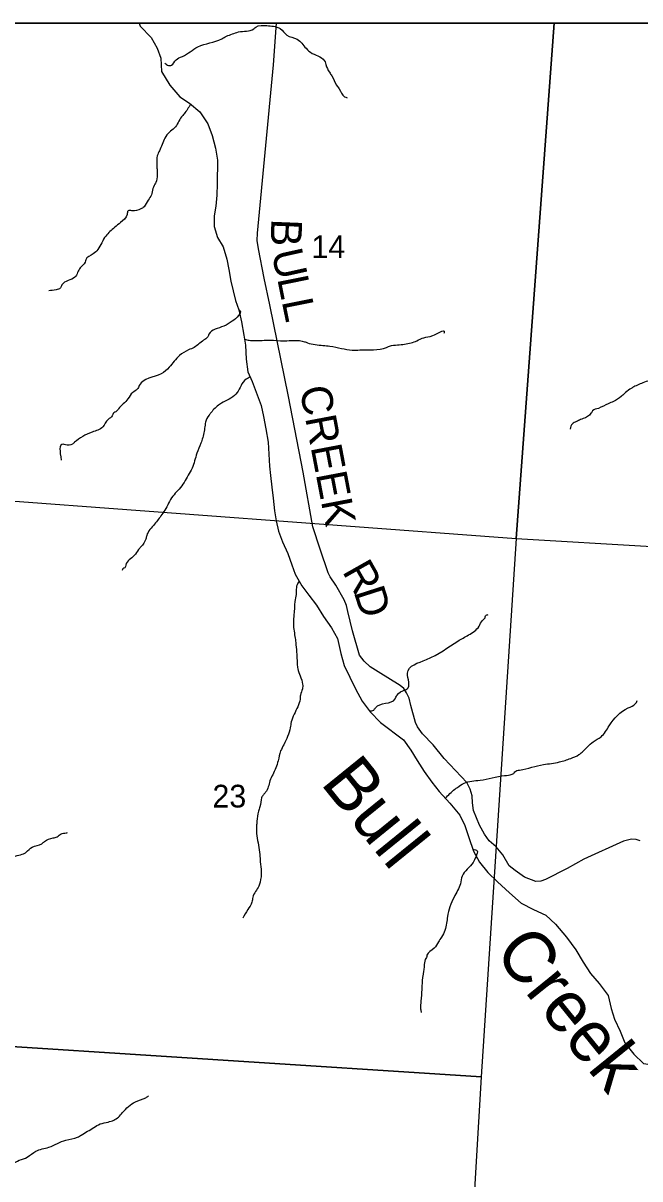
# Model space of a CAD drawing. Extents: x -13.1 to 43.1, y 0 to 22.
# Drawn here: x 5.106 to 6.242, y 18.772 to 20.9 of the extents above; entities that cross this region are included whole.
import ezdxf

# ---------------------------------------------------------------- set-up
doc = ezdxf.new("R2010")
doc.units = 0
for name, color, linetype in [('GM_X_Corporation', 7, 'Continuous'), ('GM_X_Minor_River', 7, 'Continuous'), ('GM_X_Minor_River_Text', 7, 'Continuous'), ('GM_X_Section_Text', 7, 'Continuous'), ('GM_X_Township_Road', 7, 'Continuous'), ('GM_X_Township_Road_Text', 7, 'Continuous'), ('SH_Data', 7, 'Continuous')]:
    doc.layers.add(name, color=color, linetype=linetype)

msp = doc.modelspace()

# ---------------------------------------------------------------- linework, layer by layer
at = {"layer": 'GM_X_Corporation'}
for points in [[(7.0807, 20.9), (2.1, 20.9), (2.1, 14.1), (6.6193, 14.1), (6.6994, 15.2069), (6.7531, 15.956), (6.8236, 16.9075), (6.9509, 19.0179), (7.0108, 19.8446), (7.0164, 19.8954), (7.0617, 20.6133)], [(7.0804, 20.9), (2.1, 20.9), (2.1, 14.1), (6.619, 14.1), (6.6992, 15.2074), (6.7528, 15.9566), (6.8234, 16.908), (6.8365, 17.1257), (6.9507, 19.0184), (6.9616, 19.1692), (7.0106, 19.8452), (7.0162, 19.896), (7.0615, 20.6138)], [(7.0804, 20.9), (2.1, 20.9), (2.1, 17.2152), (2.1437, 17.2135), (2.8442, 17.1637), (3.8328, 17.0966), (4.4304, 17.0575), (6.8234, 16.908), (6.8365, 17.1257), (6.9507, 19.0184), (6.9616, 19.1692), (7.0106, 19.8452), (7.0162, 19.896), (7.0615, 20.6138)], [(6.0839, 20.9), (5.0812, 20.9), (5.0243, 20.0248), (6.0143, 19.9509)], [(7.0765, 20.9), (6.0839, 20.9), (6.0143, 19.9509), (7.0143, 19.8917), (7.0727, 20.8375)], [(5.0243, 20.0248), (6.0143, 19.9509), (5.9495, 18.9594), (4.9602, 19.0234)], [(4.9602, 19.0234), (5.9495, 18.9594), (5.8912, 17.9717), (4.9031, 18.044)]]:
    msp.add_lwpolyline(points, close=True, dxfattribs=at)
at = {"layer": 'GM_X_Minor_River'}
for points in [[(5.3196, 20.9), (5.3212, 20.8944), (5.3415, 20.8738), (5.3527, 20.8539), (5.3593, 20.8357), (5.3606, 20.8106), (5.3763, 20.7855), (5.3943, 20.7641), (5.4124, 20.7525), (5.4312, 20.7365), (5.4462, 20.7143), (5.4543, 20.693), (5.4602, 20.6695), (5.4638, 20.6474), (5.4634, 20.6042), (5.4625, 20.5829), (5.4608, 20.5632), (5.4577, 20.545), (5.4575, 20.5253), (5.4642, 20.5055), (5.4746, 20.488), (5.4812, 20.4652), (5.4849, 20.4462), (5.4885, 20.4249), (5.4929, 20.4067), (5.4973, 20.3892), (5.5032, 20.3717), (5.5083, 20.3496), (5.5127, 20.3253), (5.5155, 20.3071), (5.5168, 20.2813), (5.5197, 20.2577), (5.5279, 20.2402), (5.5442, 20.1961), (5.5485, 20.1756), (5.5529, 20.1528), (5.5573, 20.1284), (5.5599, 20.0844), (5.5613, 20.067), (5.5642, 20.0457), (5.5663, 20.0252), (5.5691, 20.0016), (5.572, 19.9834), (5.5764, 19.9644), (5.5838, 19.9446), (5.5934, 19.9233), (5.6008, 19.9027), (5.6068, 19.8852), (5.6195, 19.8639), (5.6322, 19.8463), (5.6464, 19.828), (5.6591, 19.8074), (5.6741, 19.7861), (5.6853, 19.767), (5.6911, 19.7389), (5.697, 19.7168), (5.7179, 19.6742), (5.7305, 19.6513), (5.7455, 19.6314), (5.7643, 19.6123), (5.8064, 19.5801), (5.8199, 19.561), (5.8319, 19.542), (5.8446, 19.5221), (5.8588, 19.5023), (5.8723, 19.4847), (5.8918, 19.4633), (5.9105, 19.4412), (5.9195, 19.4221), (5.9269, 19.4), (5.9357, 19.3749), (5.9469, 19.3551), (5.9619, 19.336), (5.9799, 19.3184), (6.0017, 19.2985), (6.0235, 19.2794), (6.0462, 19.2678), (6.0688, 19.257), (6.0868, 19.2409), (6.1071, 19.2165), (6.1243, 19.1936), (6.1377, 19.1707), (6.1512, 19.1501), (6.1669, 19.1317), (6.1834, 19.1096), (6.1893, 19.0853), (6.1952, 19.0655), (6.2056, 19.0434)], [(6.2056, 19.0434), (6.2145, 19.0221), (6.231, 19.0015), (6.249, 18.9839), (6.2732, 18.9806), (6.2936, 18.9797), (6.3187, 18.9848), (6.3369, 18.9938), (6.3575, 19.0118), (6.3765, 19.0261), (6.3948, 19.0373), (6.4153, 19.0478), (6.4533, 19.0581), (6.4707, 19.0549), (6.4887, 19.0418), (6.5061, 19.0356), (6.5091, 19.0341)]]:
    msp.add_lwpolyline(points, dxfattribs=at)
for points in [[(5.367, 20.8262), (5.3734, 20.822), (5.3791, 20.8227), (5.3875, 20.8324), (5.3992, 20.8386), (5.4277, 20.8564), (5.4719, 20.8709), (5.4803, 20.8757), (5.4916, 20.8801), (5.5026, 20.8837), (5.5306, 20.8897), (5.5344, 20.8927), (5.5551, 20.8954), (5.5668, 20.8941), (5.5796, 20.8898), (5.5916, 20.8779), (5.6108, 20.8704), (5.627, 20.8536), (5.6386, 20.8443), (5.6623, 20.8285), (5.6637, 20.8235), (5.6701, 20.8095), (5.6746, 20.803), (5.6831, 20.7858), (5.688, 20.779), (5.6981, 20.7644), (5.703, 20.7625)], [(5.4143, 20.7509), (5.4023, 20.7327), (5.3977, 20.7275), (5.3843, 20.7065), (5.3752, 20.6991), (5.3669, 20.6882), (5.3569, 20.6649), (5.353, 20.6559), (5.3522, 20.6385), (5.3525, 20.6313), (5.3528, 20.6204), (5.3504, 20.6064), (5.347, 20.6008), (5.3435, 20.5891), (5.3423, 20.5839), (5.3362, 20.5741), (5.3286, 20.5617), (5.3225, 20.5577), (5.3063, 20.5545), (5.2991, 20.5542), (5.2972, 20.5478), (5.2854, 20.5329), (5.2744, 20.5236), (5.258, 20.5079), (5.2435, 20.4832), (5.2351, 20.475), (5.2211, 20.4642), (5.2199, 20.4597), (5.2112, 20.4496), (5.2012, 20.4323), (5.1774, 20.4179), (5.1747, 20.4123), (5.1664, 20.409), (5.1531, 20.4069)], [(6.6313, 20.522), (6.6307, 20.519), (6.6288, 20.5115), (6.6208, 20.5037), (6.6097, 20.4864), (6.601, 20.4794), (6.5919, 20.4723), (6.5782, 20.4581), (6.5732, 20.4533), (6.5652, 20.4387), (6.5602, 20.427), (6.5587, 20.4198), (6.5583, 20.4142), (6.554, 20.3961), (6.5471, 20.3882), (6.5406, 20.3751), (6.5364, 20.3699), (6.5315, 20.3654), (6.5227, 20.3534), (6.5189, 20.3493), (6.5113, 20.3388), (6.5075, 20.3355), (6.501, 20.3265), (6.4972, 20.3213), (6.4885, 20.3119), (6.4839, 20.3086), (6.4744, 20.3019), (6.4703, 20.3001), (6.4627, 20.2953), (6.4578, 20.2935), (6.4456, 20.288), (6.4305, 20.2848), (6.4264, 20.2845), (6.4203, 20.2838), (6.4173, 20.2831), (6.4139, 20.2828), (6.4063, 20.2806), (6.401, 20.2795), (6.381, 20.2681), (6.3571, 20.2609), (6.3069, 20.254), (6.2596, 20.2418), (6.2475, 20.2375), (6.2285, 20.2287), (6.2236, 20.2257), (6.2134, 20.2175), (6.2077, 20.2127), (6.1933, 20.2031), (6.1838, 20.1991), (6.1656, 20.1906), (6.155, 20.1859), (6.152, 20.1814), (6.1379, 20.1717), (6.133, 20.1699), (6.1251, 20.1662), (6.1179, 20.1622), (6.1136, 20.1524)], [(5.503, 20.3722), (5.5058, 20.3702), (5.5028, 20.3615), (5.491, 20.3511), (5.4754, 20.3419), (5.4482, 20.3271), (5.4459, 20.3222), (5.4383, 20.3159), (5.4208, 20.3029), (5.4106, 20.2982), (5.3939, 20.2878), (5.3749, 20.2662), (5.3601, 20.2543), (5.3199, 20.2329), (5.3161, 20.2258), (5.3077, 20.2198), (5.299, 20.2079), (5.2815, 20.1896), (5.2781, 20.1855), (5.2716, 20.181), (5.2701, 20.1769), (5.2625, 20.1702), (5.2526, 20.1563), (5.2329, 20.1468), (5.2007, 20.128), (5.1965, 20.1246), (5.1836, 20.1233), (5.1795, 20.1245), (5.1759, 20.0954)], [(5.5138, 20.3181), (5.5225, 20.3159), (5.5319, 20.3153), (5.5606, 20.3161), (5.5866, 20.3149), (5.6244, 20.3133), (5.6296, 20.3113), (5.6583, 20.3064), (5.6711, 20.305), (5.6922, 20.301), (5.7118, 20.2977), (5.7262, 20.2982), (5.7753, 20.3028), (5.7806, 20.305), (5.7957, 20.3074), (5.821, 20.3112), (5.8309, 20.3149), (5.8441, 20.3207), (5.8604, 20.3247), (5.8816, 20.3312), (5.8808, 20.3282)], [(5.524, 20.2484), (5.511, 20.2389), (5.5041, 20.2257), (5.495, 20.2142), (5.4677, 20.1979), (5.4521, 20.183), (5.4483, 20.1781), (5.4418, 20.1654), (5.441, 20.1597), (5.4367, 20.1367), (5.4332, 20.1262), (5.4259, 20.1078), (5.417, 20.0803), (5.4101, 20.0675), (5.3933, 20.0417), (5.3838, 20.0316), (5.3686, 20.0061), (5.3613, 19.9949), (5.348, 19.9773), (5.3335, 19.9563), (5.3319, 19.9499), (5.3228, 19.9353), (5.3186, 19.9304), (5.3106, 19.9196), (5.295, 19.9017), (5.2934, 19.8971), (5.2893, 19.8949), (5.2885, 19.8919)], [(5.6145, 19.8723), (5.6122, 19.8684), (5.6107, 19.8658), (5.6091, 19.8545), (5.6087, 19.848), (5.6067, 19.8348), (5.6047, 19.8099), (5.6038, 19.7974), (5.6066, 19.7702), (5.6081, 19.7592), (5.6095, 19.7425), (5.6108, 19.7198), (5.6119, 19.7111), (5.6163, 19.6978), (5.6208, 19.6826), (5.6203, 19.6739), (5.6168, 19.6626), (5.616, 19.6551), (5.6118, 19.6412), (5.5999, 19.613), (5.5979, 19.6024), (5.586, 19.5712), (5.5803, 19.5596), (5.5756, 19.5415), (5.5656, 19.5159), (5.5606, 19.5046), (5.5526, 19.4836), (5.5484, 19.4791), (5.5453, 19.4735), (5.5422, 19.4569), (5.5395, 19.4486), (5.5367, 19.4301), (5.5359, 19.4214), (5.5365, 19.4033), (5.542, 19.3688), (5.5426, 19.3555), (5.5444, 19.3373), (5.5424, 19.3181), (5.54, 19.3109), (5.529, 19.2903), (5.5274, 19.2812), (5.5197, 19.2674), (5.5106, 19.2516)], [(5.7443, 19.6331), (5.7518, 19.635), (5.7549, 19.6391), (5.7912, 19.6556), (5.7943, 19.662), (5.8098, 19.6724), (5.8132, 19.6738), (5.8142, 19.7029), (5.8487, 19.7278), (5.9067, 19.7621), (5.9264, 19.7732), (5.9458, 19.7892), (5.9523, 19.8), (5.9568, 19.8049), (5.958, 19.8087), (5.9629, 19.8109)], [(5.8835, 19.4724), (5.9014, 19.4892), (5.906, 19.4925), (5.9181, 19.5003), (5.9476, 19.5059), (5.9926, 19.5144), (6.0069, 19.5168), (6.0096, 19.5183), (6.0115, 19.5209), (6.0206, 19.5245), (6.0644, 19.5345), (6.0939, 19.5394), (6.1147, 19.5459), (6.1299, 19.5529), (6.1356, 19.5573), (6.1561, 19.5767), (6.1705, 19.5859), (6.1857, 19.6061), (6.2207, 19.6389), (6.2336, 19.6463), (6.2374, 19.6523)], [(4.768, 19.1884), (4.7721, 19.1929), (4.7994, 19.2088), (4.8081, 19.214), (4.8184, 19.2184), (4.8267, 19.2239), (4.8362, 19.2287), (4.8555, 19.2409), (4.8669, 19.2472), (4.8787, 19.2614), (4.895, 19.2695), (4.9083, 19.2836), (4.9261, 19.2913), (4.9314, 19.2969), (4.956, 19.309), (4.9757, 19.3141), (4.9954, 19.3259), (5.0272, 19.3356), (5.0386, 19.3445), (5.0817, 19.3625), (5.0946, 19.3672), (5.1067, 19.3704), (5.1112, 19.373), (5.1223, 19.3827), (5.1404, 19.3888), (5.1454, 19.3929), (5.1609, 19.3995), (5.1685, 19.4017), (5.1757, 19.4069), (5.1851, 19.4086), (5.1878, 19.4093)], [(5.9344, 19.3787), (5.9422, 19.3759), (5.9402, 19.3654), (5.9348, 19.3541), (5.9147, 19.3291), (5.9115, 19.3151), (5.8997, 19.2903), (5.8877, 19.2546), (5.8861, 19.2425), (5.8769, 19.2169), (5.8708, 19.2079), (5.8631, 19.1963), (5.8498, 19.1833), (5.8491, 19.1795), (5.8468, 19.1754), (5.8448, 19.1633), (5.8436, 19.1542), (5.8408, 19.1308), (5.8403, 19.1203), (5.8387, 19.0991), (5.8382, 19.0847), (5.8393, 19.0779)], [(4.9723, 18.7836), (4.9867, 18.7819), (4.9928, 18.7814), (5.0245, 18.7836), (5.0377, 18.7857), (5.0721, 18.7909), (5.0808, 18.7938), (5.0854, 18.7982), (5.1134, 18.8118), (5.1293, 18.8226), (5.1532, 18.8298), (5.1846, 18.843), (5.2061, 18.8483), (5.213, 18.8524), (5.2361, 18.8661), (5.2478, 18.8727), (5.2626, 18.8763), (5.2815, 18.8854), (5.2891, 18.8937), (5.3127, 18.9134), (5.3316, 18.921), (5.3369, 18.9244)]]:
    msp.add_spline(points, degree=3, dxfattribs=at)
at = {"layer": 'GM_X_Township_Road'}
msp.add_lwpolyline([(6.2429, 19.394), (6.2354, 19.3964), (6.2266, 19.3972), (6.2122, 19.3933), (6.1389, 19.3601), (6.1083, 19.343), (6.0681, 19.3227), (6.0594, 19.3198), (6.0503, 19.3195), (6.0295, 19.327), (6.0126, 19.3398), (6.001, 19.3483), (5.9898, 19.3682), (5.9775, 19.3832), (5.9644, 19.3944), (5.9559, 19.4067), (5.9466, 19.4231), (5.9356, 19.4498), (5.9339, 19.4639), (5.9329, 19.4768), (5.9297, 19.489), (5.9234, 19.5016), (5.8815, 19.5455), (5.8614, 19.5712), (5.8416, 19.5912), (5.8326, 19.6043), (5.829, 19.6123), (5.8203, 19.6435), (5.8171, 19.6569), (5.8123, 19.6668), (5.8074, 19.6745), (5.8007, 19.6803), (5.7601, 19.7055), (5.745, 19.7144), (5.7342, 19.7252), (5.7256, 19.7363), (5.7125, 19.7806), (5.7039, 19.8164), (5.7014, 19.8278), (5.6974, 19.8381), (5.6822, 19.8649), (5.6718, 19.8806), (5.6677, 19.8875), (5.6528, 19.931), (5.6393, 19.9726), (5.6218, 20.073), (5.5949, 20.2124), (5.5604, 20.381), (5.5497, 20.4305), (5.5395, 20.4846), (5.537, 20.4998), (5.5376, 20.5131), (5.5673, 20.8229), (5.5726, 20.9)], dxfattribs=at)
at = {"layer": 'SH_Data'}
msp.add_line((2.1, 20.9), (8.9, 20.9), dxfattribs=at)

# ---------------------------------------------------------------- texts
at = {"layer": 'GM_X_Minor_River_Text'}
for s, rotation, p in [('Bull', 308.9971, (5.6521, 19.5002)), ('Creek', 308.9966, (5.9713, 19.1876))]:
    msp.add_text(s, height=0.0947, rotation=rotation, dxfattribs=at).set_placement(p)
at = {"layer": 'GM_X_Section_Text'}
for s, p in [('14', (5.6371, 20.4675)), ('23', (5.4546, 19.4555))]:
    msp.add_text(s, height=0.04186, rotation=0, dxfattribs=at).set_placement(p)
at = {"layer": 'GM_X_Township_Road_Text'}
for s, height, rotation, p in [('B', 0.0568, 267.7513, (5.5634, 20.5404)), ('U', 0.0568, 282.5772, (5.563, 20.4781)), ('L', 0.0568, 281.3629, (5.5738, 20.4296)), ('L', 0.0568, 281.3655, (5.5822, 20.3879)), ('CREEK', 0.05682, 280.7747, (5.6149, 20.2273)), ('R', 0.0568, 299.4254, (5.6929, 19.8904)), ('D', 0.0568, 287.8152, (5.7146, 19.8525))]:
    msp.add_text(s, height=height, rotation=rotation, dxfattribs=at).set_placement(p)

doc.saveas('drawing.dxf')
